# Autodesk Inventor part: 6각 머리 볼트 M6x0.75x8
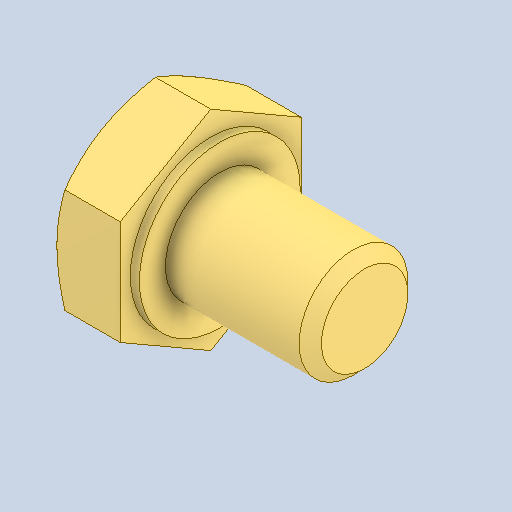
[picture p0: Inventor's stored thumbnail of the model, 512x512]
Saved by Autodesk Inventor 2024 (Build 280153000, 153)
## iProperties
Created: 2025-10
Part Number: 6각 머리 볼트 M6x0.75x8
Material: 강철, 연강
Description: 6각 머리 볼트 및 6각 머리 나사
Document SubType Name: Modeling
Designer: EDU03
Density: 7.85 g/cm^3
Appearance: 기본값
Author: jhkim
Sending System: Autodesk Inventor 2026
Preprocessor: ST-DEVELOPER v20.1
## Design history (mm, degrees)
feature "Solid1"
node "솔리드1"
